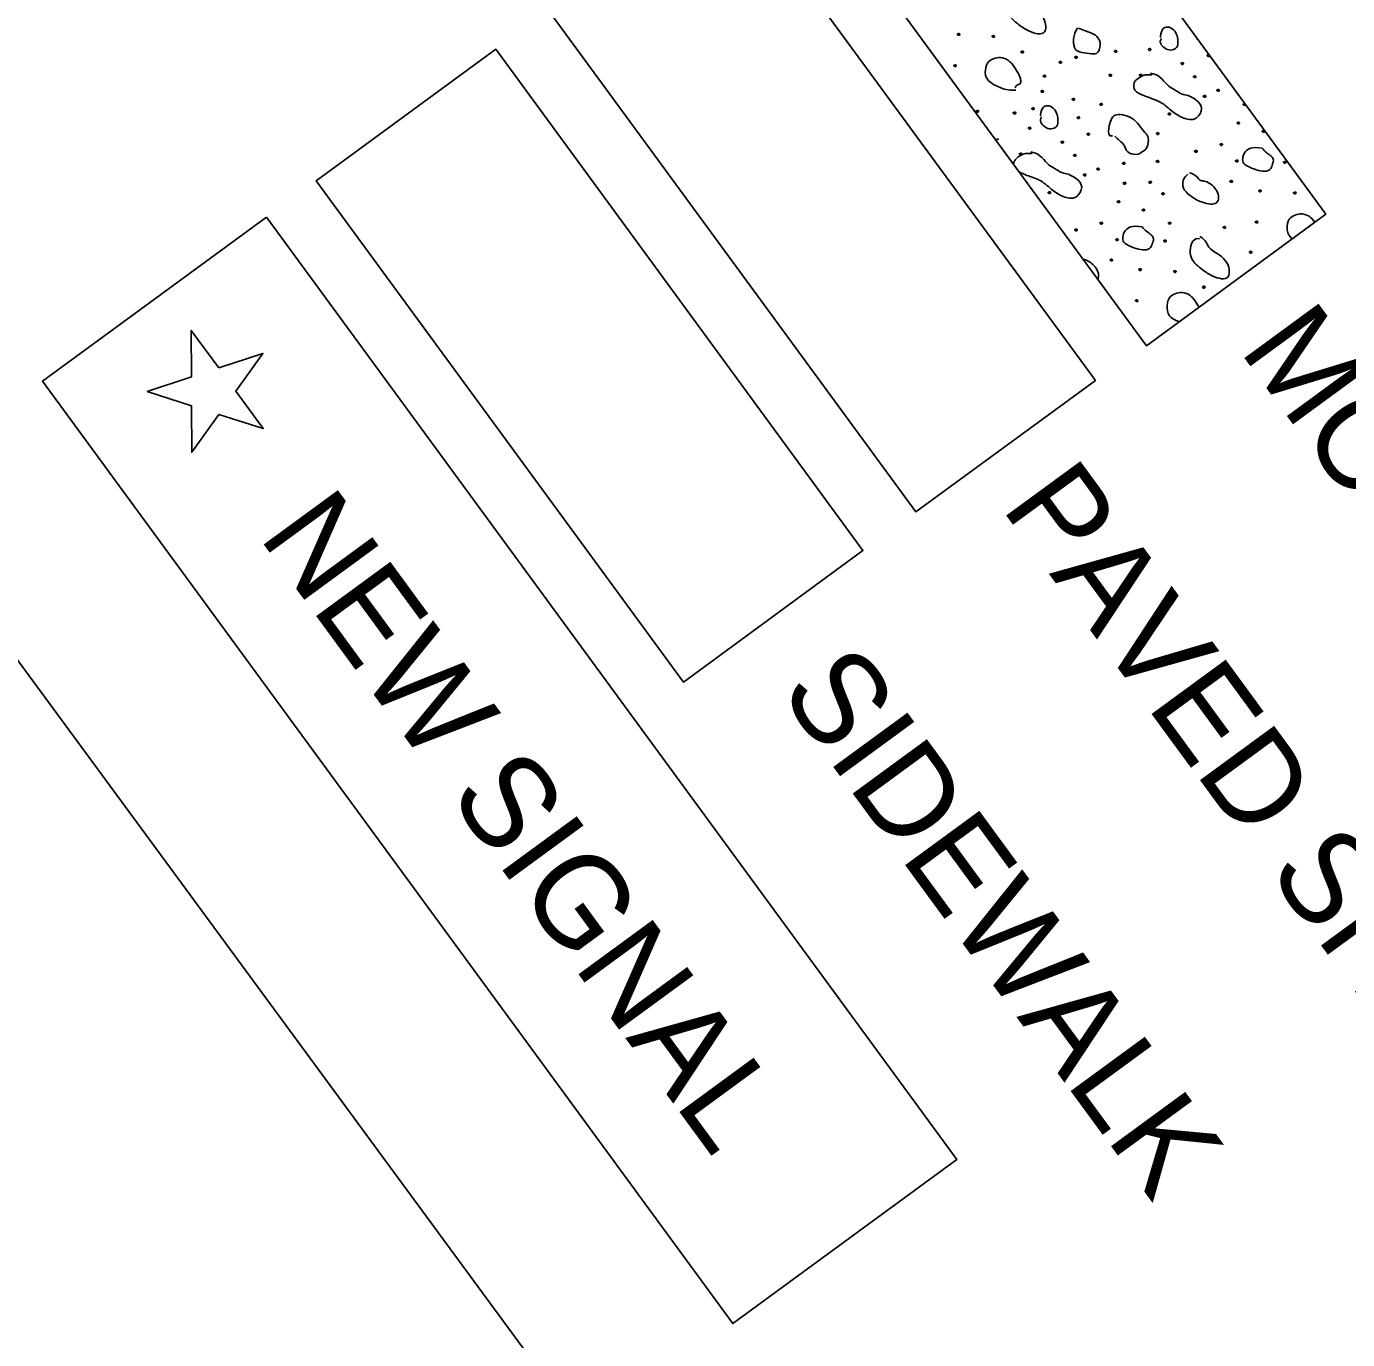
# Model space of a CAD drawing. Extents: x 1763480 to 1764420, y 711010 to 712012.
# Drawn here: x 1764255.2 to 1764305.5, y 711417.4 to 711467.4 of the extents above; entities that cross this region are included whole.
import ezdxf

# ---------------------------------------------------------------- set-up
doc = ezdxf.new("R2010")
doc.units = 0
for name, color, linetype in [('Old_Level_10', 7, 'Continuous'), ('Old_Level_40', 7, 'Continuous'), ('Prop DSN Text', 7, 'Continuous'), ('Prop Grid Mask', 7, 'Continuous'), ('Prop Horizontal Alignment Station Label', 7, 'Continuous'), ('Prop RDY Traffic Signal CELL', 7, 'Continuous'), ('Prop Shade Medium', 7, 'Continuous')]:
    doc.layers.add(name, color=color, linetype=linetype)

msp = doc.modelspace()

# ---------------------------------------------------------------- linework, layer by layer
at = {"layer": 'Old_Level_10'}
for points in [[(1764292.891, 711468.654), (1764292.774, 711468.672), (1764292.636, 711468.594), (1764292.533, 711468.325), (1764292.515, 711467.881), (1764293.008, 711467.451), (1764293.372, 711467.227), (1764293.74, 711467.099), (1764294.031, 711467.158), (1764294.031, 711467.507), (1764293.946, 711467.763), (1764293.666, 711468.06), (1764293.268, 711468.232), (1764293.126, 711468.596), (1764292.945, 711468.72), (1764292.905, 711468.741)], [(1764290.66, 711467.128), (1764290.642, 711467.11), (1764290.69, 711467.054), (1764290.767, 711467.083), (1764290.742, 711467.142), (1764290.7, 711467.136), (1764290.677, 711467.127), (1764290.665, 711467.121)], [(1764291.983, 711467.051), (1764291.964, 711467.033), (1764292.013, 711466.976), (1764292.09, 711467.008), (1764292.064, 711467.065), (1764292.022, 711467.06), (1764291.999, 711467.051), (1764291.987, 711467.045)], [(1764295.228, 711467.359), (1764295.119, 711467.15), (1764295.061, 711466.886), (1764295.109, 711466.483), (1764295.485, 711466.394), (1764295.894, 711466.355), (1764296.024, 711466.394), (1764296.095, 711466.618), (1764296.109, 711466.874), (1764295.923, 711467.095), (1764295.72, 711467.171), (1764295.538, 711467.237), (1764295.355, 711467.303), (1764295.27, 711467.337)], [(1764298.433, 711466.944), (1764298.318, 711466.826), (1764298.541, 711466.538), (1764298.791, 711466.489), (1764299.05, 711466.571), (1764299.062, 711466.86), (1764299.028, 711467.108), (1764298.853, 711467.35), (1764298.58, 711467.419), (1764298.45, 711467.283), (1764298.404, 711467.111), (1764298.391, 711467.053), (1764298.396, 711466.993)], [(1764299.788, 711466.953), (1764299.773, 711466.938), (1764299.803, 711466.914), (1764299.827, 711466.904)], [(1764299.795, 711466.948), (1764299.794, 711466.948), (1764299.793, 711466.947), (1764299.792, 711466.946)], [(1764293.082, 711466.457), (1764293.063, 711466.44), (1764293.113, 711466.38), (1764293.189, 711466.414), (1764293.164, 711466.473), (1764293.122, 711466.466), (1764293.099, 711466.458), (1764293.088, 711466.452)], [(1764296.641, 711466.481), (1764296.621, 711466.463), (1764296.67, 711466.403), (1764296.75, 711466.435), (1764296.722, 711466.495), (1764296.68, 711466.488), (1764296.658, 711466.479), (1764296.646, 711466.474)], [(1764297.934, 711466.554), (1764297.914, 711466.536), (1764297.964, 711466.478), (1764298.042, 711466.51), (1764298.017, 711466.569), (1764297.973, 711466.564), (1764297.95, 711466.554), (1764297.938, 711466.548)], [(1764290.524, 711465.939), (1764290.504, 711465.922), (1764290.554, 711465.863), (1764290.633, 711465.894), (1764290.605, 711465.955), (1764290.563, 711465.947), (1764290.541, 711465.938), (1764290.529, 711465.932)], [(1764292.891, 711464.985), (1764292.572, 711464.973), (1764292.256, 711465.078), (1764291.81, 711465.315), (1764291.688, 711465.627), (1764291.789, 711466.07), (1764292.037, 711466.185), (1764292.295, 711466.26), (1764292.622, 711466.138), (1764292.825, 711465.886), (1764293.038, 711465.534), (1764293.09, 711465.32), (1764293.046, 711465.18), (1764292.937, 711465.203), (1764292.883, 711465.126), (1764292.866, 711465.1), (1764292.858, 711465.067)], [(1764294.532, 711466.064), (1764294.513, 711466.047), (1764294.562, 711465.988), (1764294.64, 711466.019), (1764294.612, 711466.081), (1764294.571, 711466.073), (1764294.548, 711466.064), (1764294.536, 711466.058)], [(1764295.135, 711466.258), (1764295.116, 711466.241), (1764295.168, 711466.182), (1764295.243, 711466.214), (1764295.217, 711466.274), (1764295.175, 711466.266), (1764295.152, 711466.257), (1764295.14, 711466.251)], [(1764299.177, 711466.019), (1764299.158, 711466.002), (1764299.208, 711465.944), (1764299.285, 711465.976), (1764299.258, 711466.034), (1764299.216, 711466.028), (1764299.194, 711466.019), (1764299.182, 711466.013)], [(1764300.166, 711466.325), (1764300.147, 711466.308), (1764300.196, 711466.247), (1764300.265, 711466.281), (1764300.264, 711466.303), (1764300.264, 711466.308)], [(1764300.241, 711466.34), (1764300.23, 711466.339), (1764300.206, 711466.333), (1764300.183, 711466.324), (1764300.172, 711466.318)], [(1764293.93, 711465.54), (1764293.911, 711465.523), (1764293.962, 711465.463), (1764294.038, 711465.496), (1764294.012, 711465.556), (1764293.97, 711465.548), (1764293.947, 711465.539), (1764293.936, 711465.533)], [(1764296.441, 711465.574), (1764296.421, 711465.556), (1764296.471, 711465.495), (1764296.549, 711465.529), (1764296.521, 711465.589), (1764296.48, 711465.581), (1764296.457, 711465.574), (1764296.445, 711465.567)], [(1764298.071, 711465.565), (1764297.849, 711465.586), (1764297.643, 711465.518), (1764297.424, 711465.346), (1764297.373, 711465.246), (1764297.359, 711464.97), (1764297.721, 711464.759), (1764298.433, 711464.566), (1764298.843, 711464.139), (1764299.292, 711463.897), (1764299.472, 711463.865), (1764299.772, 711463.857), (1764300.055, 711464.302), (1764299.761, 711464.63), (1764299.433, 711464.8), (1764299.213, 711464.809), (1764298.911, 711465.011), (1764298.641, 711465.16), (1764298.385, 711465.522), (1764298.144, 711465.604), (1764298.019, 711465.633)], [(1764297.593, 711465.574), (1764297.574, 711465.556), (1764297.623, 711465.5), (1764297.702, 711465.529), (1764297.674, 711465.59), (1764297.632, 711465.582), (1764297.61, 711465.573), (1764297.598, 711465.567)], [(1764299.649, 711465.515), (1764299.629, 711465.498), (1764299.68, 711465.44), (1764299.757, 711465.472), (1764299.732, 711465.53), (1764299.689, 711465.524), (1764299.666, 711465.515), (1764299.654, 711465.508)], [(1764293.846, 711464.957), (1764293.826, 711464.94), (1764293.877, 711464.883), (1764293.954, 711464.914), (1764293.929, 711464.972), (1764293.886, 711464.966), (1764293.863, 711464.957), (1764293.851, 711464.95)], [(1764300.536, 711464.997), (1764300.517, 711464.98), (1764300.566, 711464.919), (1764300.646, 711464.951), (1764300.618, 711465.013), (1764300.576, 711465.005), (1764300.553, 711464.996), (1764300.542, 711464.99)], [(1764295.028, 711464.655), (1764295.008, 711464.638), (1764295.058, 711464.579), (1764295.138, 711464.611), (1764295.111, 711464.67), (1764295.068, 711464.664), (1764295.045, 711464.654), (1764295.033, 711464.648)], [(1764296.089, 711464.463), (1764296.07, 711464.446), (1764296.118, 711464.387), (1764296.197, 711464.419), (1764296.169, 711464.479), (1764296.128, 711464.472), (1764296.105, 711464.464), (1764296.093, 711464.457)], [(1764300.024, 711464.772), (1764300.005, 711464.754), (1764300.054, 711464.698), (1764300.132, 711464.728), (1764300.107, 711464.787), (1764300.064, 711464.781), (1764300.04, 711464.772), (1764300.028, 711464.766)], [(1764301.544, 711464.46), (1764301.524, 711464.442), (1764301.575, 711464.385), (1764301.636, 711464.416), (1764301.64, 711464.428)], [(1764301.607, 711464.473), (1764301.6, 711464.473), (1764301.58, 711464.466), (1764301.561, 711464.459), (1764301.549, 711464.453)], [(1764291.378, 711464.202), (1764291.358, 711464.185), (1764291.409, 711464.125), (1764291.485, 711464.158), (1764291.46, 711464.217), (1764291.418, 711464.21), (1764291.395, 711464.201), (1764291.384, 711464.196)], [(1764292.791, 711464.14), (1764292.771, 711464.123), (1764292.822, 711464.063), (1764292.9, 711464.095), (1764292.873, 711464.155), (1764292.832, 711464.147), (1764292.809, 711464.138), (1764292.797, 711464.132)], [(1764293.493, 711464.301), (1764293.473, 711464.284), (1764293.523, 711464.224), (1764293.602, 711464.257), (1764293.575, 711464.315), (1764293.533, 711464.309), (1764293.51, 711464.3), (1764293.498, 711464.294)], [(1764293.869, 711463.949), (1764293.754, 711463.83), (1764293.976, 711463.542), (1764294.227, 711463.493), (1764294.486, 711463.575), (1764294.498, 711463.864), (1764294.463, 711464.112), (1764294.289, 711464.354), (1764294.015, 711464.423), (1764293.886, 711464.287), (1764293.84, 711464.116), (1764293.826, 711464.057), (1764293.832, 711463.997)], [(1764295.223, 711463.957), (1764295.205, 711463.939), (1764295.253, 711463.882), (1764295.332, 711463.912), (1764295.305, 711463.972), (1764295.262, 711463.966), (1764295.239, 711463.957), (1764295.228, 711463.951)], [(1764296.561, 711463.241), (1764296.408, 711463.186), (1764296.411, 711463.56), (1764296.517, 711463.878), (1764296.628, 711464.062), (1764296.946, 711464.057), (1764297.341, 711463.933), (1764297.58, 711463.652), (1764297.811, 711463.336), (1764297.964, 711463.201), (1764297.904, 711462.768), (1764297.718, 711462.647), (1764297.497, 711462.492), (1764297.085, 711462.606), (1764297.055, 711462.863), (1764296.812, 711463.084), (1764296.733, 711463.158), (1764296.651, 711463.228)], [(1764298.682, 711464.098), (1764298.663, 711464.08), (1764298.711, 711464.02), (1764298.791, 711464.052), (1764298.763, 711464.112), (1764298.722, 711464.106), (1764298.698, 711464.098), (1764298.686, 711464.092)], [(1764293.369, 711463.558), (1764293.35, 711463.541), (1764293.4, 711463.482), (1764293.477, 711463.515), (1764293.452, 711463.573), (1764293.409, 711463.568), (1764293.386, 711463.558), (1764293.374, 711463.552)], [(1764301.314, 711463.752), (1764301.295, 711463.734), (1764301.344, 711463.678), (1764301.421, 711463.71), (1764301.395, 711463.766), (1764301.353, 711463.761), (1764301.33, 711463.752), (1764301.318, 711463.746)], [(1764302.263, 711463.439), (1764302.244, 711463.421), (1764302.294, 711463.361), (1764302.371, 711463.395), (1764302.344, 711463.454), (1764302.303, 711463.447), (1764302.28, 711463.438), (1764302.268, 711463.432)], [(1764292.149, 711463.111), (1764292.14, 711463.098), (1764292.157, 711463.079), (1764292.169, 711463.071)], [(1764292.235, 711463.119), (1764292.232, 711463.121), (1764292.215, 711463.127), (1764292.189, 711463.118), (1764292.166, 711463.109), (1764292.154, 711463.104)], [(1764294.613, 711463.023), (1764294.594, 711463.006), (1764294.643, 711462.948), (1764294.721, 711462.98), (1764294.694, 711463.039), (1764294.652, 711463.032), (1764294.629, 711463.023), (1764294.617, 711463.017)], [(1764295.602, 711463.329), (1764295.583, 711463.312), (1764295.632, 711463.252), (1764295.711, 711463.284), (1764295.683, 711463.345), (1764295.642, 711463.337), (1764295.619, 711463.328), (1764295.607, 711463.322)], [(1764298.243, 711463.354), (1764298.223, 711463.337), (1764298.274, 711463.28), (1764298.35, 711463.311), (1764298.325, 711463.369), (1764298.282, 711463.364), (1764298.259, 711463.355), (1764298.248, 711463.349)], [(1764300.66, 711462.937), (1764300.642, 711462.919), (1764300.69, 711462.862), (1764300.769, 711462.892), (1764300.741, 711462.951), (1764300.699, 711462.945), (1764300.677, 711462.936), (1764300.665, 711462.93)], [(1764293.506, 711462.569), (1764293.285, 711462.59), (1764293.079, 711462.522), (1764292.866, 711462.355), (1764292.817, 711462.267), (1764292.804, 711462.157)], [(1764293.028, 711462.579), (1764293.01, 711462.561), (1764293.058, 711462.504), (1764293.138, 711462.533), (1764293.11, 711462.594), (1764293.068, 711462.587), (1764293.045, 711462.578), (1764293.034, 711462.572)], [(1764293.016, 711461.867), (1764293.032, 711461.859), (1764293.27, 711461.735), (1764293.868, 711461.57), (1764294.278, 711461.143), (1764294.728, 711460.901), (1764294.908, 711460.869), (1764295.208, 711460.862), (1764295.49, 711461.306), (1764295.197, 711461.635), (1764294.869, 711461.804), (1764294.648, 711461.814), (1764294.346, 711462.016), (1764294.076, 711462.164), (1764293.821, 711462.526), (1764293.579, 711462.608), (1764293.455, 711462.637)], [(1764295.084, 711462.52), (1764295.064, 711462.502), (1764295.116, 711462.445), (1764295.192, 711462.476), (1764295.167, 711462.534), (1764295.125, 711462.528), (1764295.102, 711462.519), (1764295.089, 711462.512)], [(1764299.693, 711462.679), (1764299.674, 711462.661), (1764299.724, 711462.601), (1764299.801, 711462.634), (1764299.773, 711462.694), (1764299.733, 711462.686), (1764299.709, 711462.678), (1764299.698, 711462.673)], [(1764302.26, 711462.773), (1764302.083, 711462.806), (1764301.779, 711462.81), (1764301.548, 711462.578), (1764301.504, 711462.313), (1764301.556, 711462.142), (1764301.958, 711461.969), (1764302.286, 711461.87), (1764302.58, 711461.923), (1764302.641, 711462.125), (1764302.722, 711462.325), (1764302.62, 711462.474), (1764302.441, 711462.579), (1764302.304, 711462.718), (1764302.26, 711462.773)], [(1764295.972, 711462.001), (1764295.953, 711461.984), (1764296.001, 711461.924), (1764296.081, 711461.956), (1764296.053, 711462.017), (1764296.012, 711462.009), (1764295.989, 711462), (1764295.977, 711461.994)], [(1764296.95, 711462.221), (1764296.931, 711462.203), (1764296.982, 711462.144), (1764297.057, 711462.176), (1764297.032, 711462.236), (1764296.99, 711462.228), (1764296.967, 711462.221), (1764296.955, 711462.214)], [(1764298.234, 711462.291), (1764298.214, 711462.274), (1764298.265, 711462.215), (1764298.341, 711462.248), (1764298.316, 711462.307), (1764298.274, 711462.3), (1764298.251, 711462.29), (1764298.239, 711462.284)], [(1764301.253, 711462.309), (1764301.234, 711462.291), (1764301.284, 711462.231), (1764301.361, 711462.265), (1764301.334, 711462.324), (1764301.292, 711462.317), (1764301.269, 711462.309), (1764301.258, 711462.303)], [(1764303.08, 711462.262), (1764303.062, 711462.244), (1764303.11, 711462.185), (1764303.188, 711462.218), (1764303.161, 711462.277), (1764303.119, 711462.271), (1764303.097, 711462.262), (1764303.085, 711462.256)], [(1764295.46, 711461.776), (1764295.441, 711461.759), (1764295.49, 711461.703), (1764295.568, 711461.732), (1764295.542, 711461.791), (1764295.499, 711461.786), (1764295.476, 711461.777), (1764295.464, 711461.77)], [(1764296.979, 711461.464), (1764296.96, 711461.446), (1764297.01, 711461.388), (1764297.088, 711461.42), (1764297.06, 711461.479), (1764297.019, 711461.472), (1764296.996, 711461.463), (1764296.984, 711461.457)], [(1764297.957, 711461.503), (1764297.938, 711461.486), (1764297.987, 711461.426), (1764298.066, 711461.458), (1764298.039, 711461.517), (1764297.997, 711461.511), (1764297.974, 711461.502), (1764297.963, 711461.496)], [(1764299.434, 711461.784), (1764299.358, 711461.701), (1764299.266, 711461.647), (1764299.204, 711461.311), (1764299.399, 711461.038), (1764299.834, 711460.755), (1764300.15, 711460.659), (1764300.442, 711460.621), (1764300.612, 711460.753), (1764300.609, 711461.034), (1764300.479, 711461.263), (1764300.272, 711461.438), (1764300.054, 711461.544), (1764299.877, 711461.522), (1764299.796, 711461.694), (1764299.638, 711461.78), (1764299.574, 711461.814), (1764299.502, 711461.835)], [(1764301.038, 711461.532), (1764301.019, 711461.514), (1764301.069, 711461.455), (1764301.147, 711461.487), (1764301.12, 711461.546), (1764301.078, 711461.54), (1764301.055, 711461.531), (1764301.044, 711461.525)], [(1764294.118, 711461.102), (1764294.098, 711461.085), (1764294.147, 711461.024), (1764294.226, 711461.057), (1764294.199, 711461.116), (1764294.157, 711461.11), (1764294.134, 711461.102), (1764294.122, 711461.096)], [(1764298.44, 711461.058), (1764298.421, 711461.041), (1764298.471, 711460.984), (1764298.547, 711461.015), (1764298.521, 711461.076), (1764298.479, 711461.068), (1764298.456, 711461.059), (1764298.444, 711461.052)], [(1764302.138, 711461.172), (1764302.12, 711461.154), (1764302.168, 711461.098), (1764302.246, 711461.127), (1764302.22, 711461.186), (1764302.178, 711461.18), (1764302.155, 711461.171), (1764302.144, 711461.165)], [(1764303.461, 711461.095), (1764303.442, 711461.077), (1764303.491, 711461.02), (1764303.568, 711461.052), (1764303.542, 711461.109), (1764303.5, 711461.104), (1764303.477, 711461.095), (1764303.465, 711461.089)], [(1764296.749, 711460.756), (1764296.731, 711460.738), (1764296.78, 711460.682), (1764296.857, 711460.714), (1764296.83, 711460.77), (1764296.788, 711460.765), (1764296.765, 711460.756), (1764296.754, 711460.75)], [(1764297.699, 711460.443), (1764297.679, 711460.426), (1764297.73, 711460.366), (1764297.807, 711460.399), (1764297.78, 711460.459), (1764297.738, 711460.451), (1764297.716, 711460.442), (1764297.704, 711460.436)], [(1764296.096, 711459.941), (1764296.077, 711459.923), (1764296.126, 711459.867), (1764296.205, 711459.896), (1764296.177, 711459.956), (1764296.135, 711459.949), (1764296.112, 711459.94), (1764296.101, 711459.934)], [(1764298.694, 711459.942), (1764298.675, 711459.923), (1764298.725, 711459.868), (1764298.801, 711459.898), (1764298.775, 711459.958), (1764298.733, 711459.951), (1764298.71, 711459.942), (1764298.698, 711459.935)], [(1764302.002, 711459.983), (1764301.983, 711459.966), (1764302.032, 711459.906), (1764302.111, 711459.938), (1764302.083, 711459.999), (1764302.042, 711459.991), (1764302.019, 711459.982), (1764302.007, 711459.976)], [(1764303.403, 711459.315), (1764303.255, 711459.454), (1764303.176, 711459.715), (1764303.267, 711460.113), (1764303.515, 711460.229), (1764303.774, 711460.304), (1764304.081, 711460.189), (1764304.178, 711460.072), (1764304.269, 711459.949)], [(1764295.129, 711459.683), (1764295.109, 711459.665), (1764295.16, 711459.605), (1764295.237, 711459.638), (1764295.209, 711459.699), (1764295.168, 711459.69), (1764295.145, 711459.683), (1764295.133, 711459.677)], [(1764297.695, 711459.777), (1764297.519, 711459.81), (1764297.214, 711459.815), (1764296.984, 711459.582), (1764296.94, 711459.317), (1764296.992, 711459.146), (1764297.393, 711458.973), (1764297.721, 711458.874), (1764298.015, 711458.928), (1764298.077, 711459.129), (1764298.158, 711459.329), (1764298.055, 711459.479), (1764297.877, 711459.583), (1764297.74, 711459.722), (1764297.695, 711459.777)], [(1764299.878, 711459.328), (1764299.76, 711459.346), (1764299.623, 711459.267), (1764299.519, 711458.999), (1764299.502, 711458.555), (1764299.995, 711458.125), (1764300.359, 711457.901), (1764300.727, 711457.773), (1764301.017, 711457.832), (1764301.018, 711458.181), (1764300.932, 711458.436), (1764300.652, 711458.733), (1764300.255, 711458.905), (1764300.113, 711459.27), (1764299.932, 711459.393), (1764299.891, 711459.415)], [(1764300.78, 711459.78), (1764300.76, 711459.763), (1764300.81, 711459.704), (1764300.888, 711459.735), (1764300.861, 711459.795), (1764300.819, 711459.788), (1764300.796, 711459.779), (1764300.785, 711459.773)], [(1764296.689, 711459.313), (1764296.669, 711459.296), (1764296.72, 711459.236), (1764296.797, 711459.27), (1764296.769, 711459.328), (1764296.728, 711459.322), (1764296.705, 711459.313), (1764296.693, 711459.307)], [(1764298.516, 711459.266), (1764298.498, 711459.248), (1764298.545, 711459.19), (1764298.624, 711459.222), (1764298.597, 711459.281), (1764298.555, 711459.275), (1764298.532, 711459.266), (1764298.52, 711459.26)], [(1764296.007, 711457.784), (1764296.031, 711457.824), (1764296.062, 711458.003), (1764295.914, 711458.267), (1764295.708, 711458.442), (1764295.518, 711458.535), (1764295.489, 711458.532), (1764295.462, 711458.528)], [(1764296.474, 711458.536), (1764296.454, 711458.519), (1764296.504, 711458.46), (1764296.583, 711458.492), (1764296.556, 711458.55), (1764296.514, 711458.544), (1764296.491, 711458.535), (1764296.479, 711458.529)], [(1764301.782, 711458.837), (1764301.763, 711458.819), (1764301.813, 711458.76), (1764301.891, 711458.791), (1764301.863, 711458.852), (1764301.821, 711458.844), (1764301.799, 711458.835), (1764301.787, 711458.829)], [(1764297.574, 711458.176), (1764297.556, 711458.158), (1764297.604, 711458.102), (1764297.681, 711458.131), (1764297.656, 711458.191), (1764297.614, 711458.184), (1764297.591, 711458.175), (1764297.579, 711458.169)], [(1764298.896, 711458.099), (1764298.878, 711458.081), (1764298.927, 711458.024), (1764299.004, 711458.056), (1764298.978, 711458.113), (1764298.936, 711458.108), (1764298.913, 711458.099), (1764298.901, 711458.093)], [(1764299.996, 711457.505), (1764299.976, 711457.488), (1764300.027, 711457.428), (1764300.103, 711457.462), (1764300.078, 711457.522), (1764300.036, 711457.515), (1764300.013, 711457.506), (1764300.001, 711457.5)], [(1764297.438, 711456.987), (1764297.418, 711456.97), (1764297.468, 711456.911), (1764297.547, 711456.942), (1764297.519, 711457.003), (1764297.477, 711456.995), (1764297.455, 711456.986), (1764297.443, 711456.98)], [(1764299.109, 711456.17), (1764299.045, 711456.196), (1764298.758, 711456.275), (1764298.602, 711456.675), (1764298.703, 711457.118), (1764298.951, 711457.233), (1764299.209, 711457.309), (1764299.536, 711457.186), (1764299.685, 711456.993), (1764299.823, 711456.786), (1764299.861, 711456.72)]]:
    msp.add_open_spline(points, degree=3, dxfattribs=at)
at = {"layer": 'Old_Level_40'}
for points in [[(1764304.693, 711460.26), (1764290.713, 711479.349), (1764283.879, 711474.344), (1764297.859, 711455.254)], [(1764295.915, 711453.931), (1764281.935, 711473.02), (1764275.101, 711468.015), (1764289.081, 711448.926)], [(1764287.067, 711447.451), (1764273.087, 711466.54), (1764266.253, 711461.535), (1764280.233, 711442.446)]]:
    msp.add_lwpolyline(points, close=True, dxfattribs=at)
at = {"layer": 'Prop Grid Mask'}
msp.add_lwpolyline([(1764264.365, 711460.147), (1764290.64, 711424.27), (1764282.11, 711418.022), (1764255.834, 711453.9)], close=True, dxfattribs=at)
at = {"layer": 'Prop Horizontal Alignment Station Label'}
msp.add_lwpolyline([(1763957.767, 711941.041), (1764052.937, 711811.602), (1764008.237, 711778.736), (1764295.846, 711387.562), (1764241.648, 711347.713), (1764301.877, 711263.144), (1763979.819, 711026.353), (1763792.923, 711280.549), (1763982.563, 711419.98), (1763871.457, 711571.095), (1763681.817, 711431.664), (1763535.546, 711630.605)], close=True, dxfattribs=at)
at = {"layer": 'Prop RDY Traffic Signal CELL'}
msp.add_lwpolyline([(1764273.087, 711466.54), (1764287.067, 711447.451), (1764280.233, 711442.446), (1764266.253, 711461.535)], close=True, dxfattribs=at)
msp.add_lwpolyline([(1764262.542, 711454.406), (1764261.497, 711455.832), (1764261.504, 711454.064), (1764259.821, 711453.51), (1764261.509, 711452.969), (1764261.516, 711451.198), (1764262.551, 711452.635), (1764264.236, 711452.095), (1764263.19, 711453.522), (1764264.225, 711454.96), (1764262.542, 711454.406)], dxfattribs=at)
at = {"layer": 'Prop Shade Medium'}
msp.add_lwpolyline([(1764295.915, 711453.931), (1764281.935, 711473.02), (1764275.101, 711468.015), (1764289.081, 711448.926), (1764295.915, 711453.931)], dxfattribs=at)

# ---------------------------------------------------------------- texts
at = {"layer": 'Prop DSN Text'}
for s, p in [('MONOLITHIC ISLAND', (1764301.359, 711455.094)), ('PAVED SHOULDER', (1764292.292, 711449.097)), ('NEW SIGNAL', (1764264.028, 711447.995)), ('SIDEWALK', (1764283.837, 711442.081))]:
    msp.add_text(s, height=3.5, rotation=306.2176, dxfattribs=at).set_placement(p)

doc.saveas('drawing.dxf')
